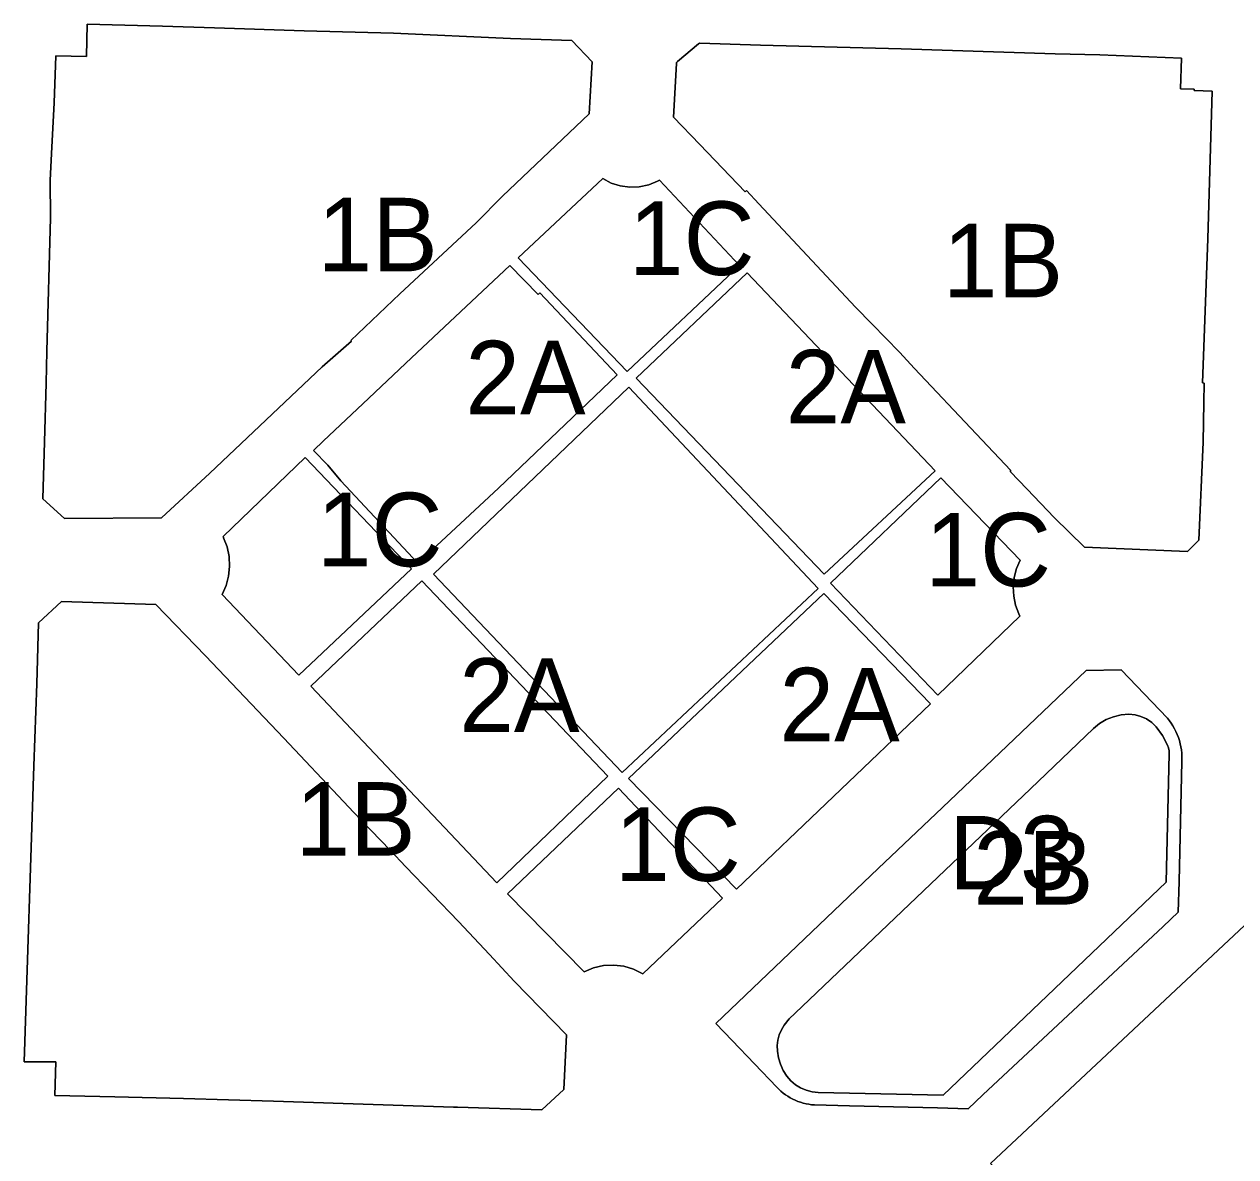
# Model space of a CAD drawing. Extents: x 598968 to 613553, y 4409678 to 4430833.
# Drawn here: x 607200.1 to 607397.8, y 4415081 to 4415265.8 of the extents above; entities that cross this region are included whole.
import ezdxf

# ---------------------------------------------------------------- set-up
doc = ezdxf.new("R2010")
doc.units = 0
for name, color, linetype in [('1', 7, 'Continuous'), ('ZONA 1B. Illes de cases extensives - ANNEX III C', 7, 'Continuous'), ('ZONA 1C. Cases aïllades centrals - ANNEX III C', 7, 'Continuous'), ('ZONA 2A. Fileres de cases - ANNEX III C', 7, 'Continuous'), ('ZONA 2B. Blocs aïllats - ANNEX III C', 7, 'Continuous'), ('ZONES URBANES. Espai lliure privat', 7, 'Continuous')]:
    doc.layers.add(name, color=color, linetype=linetype)

msp = doc.modelspace()

# ---------------------------------------------------------------- linework, layer by layer
at = {"layer": '1'}
for points in [[(607289.4816, 4415263.0751), (607292.7716, 4415259.6052), (607292.2616, 4415251.1253), (607278.1618, 4415237.6852), (607273.8319, 4415233.3751), (607261.3971, 4415221.76), (607253.412, 4415214.1444), (607253.4972, 4415214.055), (607248.7123, 4415209.8549), (607230.4076, 4415192.5248), (607222.4927, 4415185.2347), (607206.7029, 4415185.1145), (607203.1429, 4415188.3444), (607203.4029, 4415197.6243), (607203.6828, 4415207.1641), (607203.7828, 4415212.4141), (607204.3869, 4415234.1644), (607204.3627, 4415240.2838), (607204.6327, 4415245.6737), (607205.0027, 4415252.9437), (607205.2526, 4415260.6136), (607210.2526, 4415260.4937), (607210.388, 4415265.7535), (607222.6524, 4415265.4638), (607231.1423, 4415265.174), (607245.8021, 4415264.6743), (607260.337, 4415264.2845), (607279.4417, 4415263.4049)], [(607393.9298, 4415254.85), (607393.2304, 4415230.7274), (607392.3679, 4415207.226), (607392.6436, 4415207.2159), (607392.5805, 4415204.0277), (607392.4906, 4415197.5877), (607391.7406, 4415181.5479), (607389.8907, 4415179.7279), (607373.1009, 4415180.4576), (607368.1759, 4415185.2974), (607363.7409, 4415189.8873), (607360.961, 4415192.7772), (607361.111, 4415192.9172), (607355.411, 4415198.947), (607345.3911, 4415209.6067), (607342.9411, 4415212.2366), (607338.4811, 4415216.7965), (607335.7412, 4415219.6164), (607319.9713, 4415236.4659), (607317.9663, 4415238.6509), (607317.7413, 4415238.4159), (607310.3314, 4415246.1357), (607306.0515, 4415250.6155), (607306.5114, 4415259.3254), (607306.5244, 4415259.4098), (607306.5508, 4415259.491), (607306.5898, 4415259.567), (607306.6404, 4415259.6357), (607306.7014, 4415259.6954), (607310.1213, 4415262.5455), (607310.161, 4415262.5816), (607310.2062, 4415262.6103), (607310.2556, 4415262.6309), (607310.3078, 4415262.6428), (607310.3613, 4415262.6455), (607320.2212, 4415262.3157), (607343.2109, 4415261.7261), (607368.3106, 4415260.9464), (607375.6205, 4415260.7767), (607388.9288, 4415260.2269), (607388.7504, 4415255.227), (607391.0204, 4415255.137), (607391.0152, 4415254.9469)], [(607297.3677, 4415239.3668), (607298.9127, 4415239.1561), (607300.4708, 4415239.2157), (607301.9951, 4415239.5436), (607303.4397, 4415240.1301), (607303.7615, 4415240.2856), (607316.8414, 4415226.406), (607298.5017, 4415209.1159), (607280.6919, 4415227.6253), (607294.5016, 4415240.5654), (607295.8825, 4415239.8414)], [(607279.3519, 4415226.4053), (607283.9418, 4415221.6455), (607284.2518, 4415221.9355), (607296.8515, 4415208.543), (607277.482, 4415190.0357), (607264.3478, 4415177.7939), (607251.7623, 4415191.2452), (607249.6224, 4415193.7966), (607247.3124, 4415196.1951), (607248.9523, 4415197.7951), (607255.3672, 4415203.8301), (607263.3221, 4415211.3202)], [(607348.7411, 4415192.867), (607330.6378, 4415176.0424), (607299.9517, 4415208.0259), (607318.0414, 4415225.186)], [(607329.6297, 4415173.7121), (607297.6971, 4415143.6501), (607266.8797, 4415176.031), (607298.7815, 4415206.5156)], [(607329.6297, 4415173.7121), (607298.7815, 4415206.5156), (607266.8797, 4415176.031), (607297.6971, 4415143.6501)], [(607263.2922, 4415176.9156), (607244.8925, 4415159.5654), (607232.4026, 4415172.7051), (607233.0383, 4415174.1696), (607233.4433, 4415175.7139), (607233.608, 4415177.3018), (607233.5285, 4415178.8963), (607233.2068, 4415180.46), (607232.6504, 4415181.9564), (607232.6177, 4415182.0583), (607232.5732, 4415182.1556), (607245.9601, 4415195.0655)], [(607362.551, 4415169.1475), (607349.1912, 4415156.2774), (607331.6714, 4415174.5569), (607349.6711, 4415191.767), (607362.601, 4415178.3274), (607362.01, 4415176.9338), (607361.6349, 4415175.4672), (607361.4844, 4415173.9609), (607361.5617, 4415172.4491), (607361.8652, 4415170.9662), (607362.3879, 4415169.5455)], [(607295.312, 4415143.0766), (607277.1976, 4415125.6671), (607246.8725, 4415157.7355), (607265.0122, 4415174.9256)], [(607347.9813, 4415154.8474), (607316.3317, 4415124.6272), (607298.6819, 4415142.6866), (607330.5714, 4415172.8569)], [(607288.1523, 4415091.9271), (607284.5419, 4415088.6349), (607270.8298, 4415089.0581), (607270.1698, 4415089.0797), (607258.6526, 4415089.4566), (607240.7828, 4415090.0362), (607226.123, 4415090.4859), (607214.9199, 4415090.7307), (607205.0833, 4415090.9455), (607205.2432, 4415096.4355), (607200.1133, 4415096.4854), (607201.6731, 4415144.7648), (607202.1454, 4415158.1491), (607202.433, 4415168.0746), (607206.2159, 4415171.5473), (607221.5728, 4415171.0749), (607229.6627, 4415162.7051), (607242.4526, 4415149.2755), (607252.2025, 4415138.9258), (607253.8725, 4415137.1359), (607255.1262, 4415135.8487), (607259.8425, 4415131.006), (607262.3724, 4415128.2962), (607270.9424, 4415119.3664), (607276.0323, 4415113.9566), (607280.0723, 4415109.6267), (607288.5922, 4415100.877)], [(607379.069, 4415160.3997), (607386.6388, 4415152.5401), (607386.9588, 4415152.1203), (607387.2588, 4415151.7003), (607387.5388, 4415151.2603), (607387.7888, 4415150.8003), (607388.0188, 4415150.3303), (607388.2288, 4415149.8603), (607388.4188, 4415149.3703), (607388.5788, 4415148.8703), (607388.7088, 4415148.3703), (607388.8288, 4415147.8603), (607388.9088, 4415147.3404), (607388.9688, 4415146.8204), (607388.9988, 4415146.3005), (607388.9988, 4415145.4705), (607388.529, 4415125.8809), (607388.409, 4415120.8711), (607385.9191, 4415118.551), (607356.54, 4415091.0505), (607354.1101, 4415088.7805), (607349.1302, 4415088.9303), (607334.7806, 4415089.2798), (607329.0407, 4415089.4196), (607328.5807, 4415089.4595), (607328.1207, 4415089.5295), (607327.6707, 4415089.6195), (607327.2207, 4415089.7295), (607326.7807, 4415089.8595), (607326.3408, 4415090.0095), (607325.9108, 4415090.1895), (607325.5008, 4415090.3795), (607325.0908, 4415090.5994), (607324.6908, 4415090.8394), (607324.3108, 4415091.0993), (607323.9408, 4415091.3693), (607323.5808, 4415091.6693), (607323.2408, 4415091.9793), (607322.9208, 4415092.3093), (607315.6309, 4415099.9489), (607312.971, 4415102.7387), (607339.4602, 4415127.9791), (607349.9298, 4415137.9591), (607373.389, 4415160.3095)], [(607314.0618, 4415123.1772), (607301.032, 4415110.8171), (607299.5446, 4415111.5638), (607297.9509, 4415112.0431), (607296.2983, 4415112.2407), (607294.6364, 4415112.1506), (607293.0148, 4415111.7756), (607291.4821, 4415111.1269), (607278.9422, 4415123.8465), (607297.052, 4415141.1266)], [(607406.2436, 4415028.3837), (607357.7665, 4415079.882), (607400.0659, 4415119.5323), (607448.0291, 4415068.3834), (607494.246, 4415066.8294), (607500.435, 4415062.8748), (607499.825, 4415051.5949), (607498.0651, 4415043.685), (607491.9652, 4415032.845), (607490.0452, 4415030.475), (607482.0353, 4415016.935), (607480.3354, 4415012.755), (607477.1754, 4415002.7051), (607475.9355, 4414997.5151), (607474.8055, 4414990.8552), (607474.0155, 4414988.7052), (607472.5456, 4414987.3552), (607471.0256, 4414986.6852), (607467.1856, 4414986.4151), (607404.8763, 4414988.4539)], [(607448.0291, 4415068.3834), (607400.0659, 4415119.5323), (607357.7665, 4415079.882), (607406.2436, 4415028.3837), (607406.4361, 4415034.0034), (607442.4385, 4415068.5714)]]:
    msp.add_lwpolyline(points, close=True, dxfattribs=at)
at = {"layer": 'ZONA 1B. Illes de cases extensives - ANNEX III C'}
for points in [[(607289.4816, 4415263.0751), (607279.4417, 4415263.4049), (607260.337, 4415264.2845), (607245.8021, 4415264.6743), (607231.1423, 4415265.174), (607222.6524, 4415265.4638), (607210.388, 4415265.7535), (607210.2526, 4415260.4937), (607205.2526, 4415260.6136), (607205.0027, 4415252.9437), (607204.6327, 4415245.6737), (607204.3627, 4415240.2838), (607204.3869, 4415234.1644), (607203.7828, 4415212.4141), (607203.6828, 4415207.1641), (607203.4029, 4415197.6243), (607203.1429, 4415188.3444), (607206.7029, 4415185.1145), (607222.4927, 4415185.2347), (607230.4076, 4415192.5248), (607248.7123, 4415209.8549), (607253.4972, 4415214.055), (607253.412, 4415214.1444), (607261.3971, 4415221.76), (607273.8319, 4415233.3751), (607278.1618, 4415237.6852), (607292.2616, 4415251.1253), (607292.7716, 4415259.6052)], [(607393.9298, 4415254.85), (607391.0152, 4415254.9469), (607391.0204, 4415255.137), (607388.7504, 4415255.227), (607388.9288, 4415260.2269), (607375.6205, 4415260.7767), (607368.3106, 4415260.9464), (607343.2109, 4415261.7261), (607320.2212, 4415262.3157), (607310.3613, 4415262.6455), (607310.3078, 4415262.6428), (607310.2556, 4415262.6309), (607310.2062, 4415262.6103), (607310.161, 4415262.5816), (607310.1213, 4415262.5455), (607306.7014, 4415259.6954), (607306.6404, 4415259.6357), (607306.5898, 4415259.567), (607306.5508, 4415259.491), (607306.5244, 4415259.4098), (607306.5114, 4415259.3254), (607306.0515, 4415250.6155), (607310.3314, 4415246.1357), (607317.7413, 4415238.4159), (607317.9663, 4415238.6509), (607319.9713, 4415236.4659), (607335.7412, 4415219.6164), (607338.4811, 4415216.7965), (607342.9411, 4415212.2366), (607345.3911, 4415209.6067), (607355.411, 4415198.947), (607361.111, 4415192.9172), (607360.961, 4415192.7772), (607363.7409, 4415189.8873), (607368.1759, 4415185.2974), (607373.1009, 4415180.4576), (607389.8907, 4415179.7279), (607391.7406, 4415181.5479), (607392.4906, 4415197.5877), (607392.5805, 4415204.0277), (607392.6436, 4415207.2159), (607392.3679, 4415207.226), (607393.2304, 4415230.7274)], [(607288.1523, 4415091.9271), (607288.5922, 4415100.877), (607280.0723, 4415109.6267), (607276.0323, 4415113.9566), (607270.9424, 4415119.3664), (607262.3724, 4415128.2962), (607259.8425, 4415131.006), (607255.1262, 4415135.8487), (607253.8725, 4415137.1359), (607252.2025, 4415138.9258), (607242.4526, 4415149.2755), (607229.6627, 4415162.7051), (607221.5728, 4415171.0749), (607206.2159, 4415171.5473), (607202.433, 4415168.0746), (607202.1454, 4415158.1491), (607201.6731, 4415144.7648), (607200.1133, 4415096.4854), (607205.2432, 4415096.4355), (607205.0833, 4415090.9455), (607214.9199, 4415090.7307), (607226.123, 4415090.4859), (607240.7828, 4415090.0362), (607258.6526, 4415089.4566), (607270.1698, 4415089.0797), (607270.8298, 4415089.0581), (607284.5419, 4415088.6349)]]:
    msp.add_lwpolyline(points, close=True, dxfattribs=at)
at = {"layer": 'ZONA 1C. Cases aïllades centrals - ANNEX III C'}
for points in [[(607297.3677, 4415239.3668), (607295.8825, 4415239.8414), (607294.5016, 4415240.5654), (607280.6919, 4415227.6253), (607298.5017, 4415209.1159), (607316.8414, 4415226.406), (607303.7615, 4415240.2856), (607303.4397, 4415240.1301), (607301.9951, 4415239.5436), (607300.4708, 4415239.2157), (607298.9127, 4415239.1561)], [(607263.2922, 4415176.9156), (607245.9601, 4415195.0655), (607232.5732, 4415182.1556), (607232.6177, 4415182.0583), (607232.6504, 4415181.9564), (607233.2068, 4415180.46), (607233.5285, 4415178.8963), (607233.608, 4415177.3018), (607233.4433, 4415175.7139), (607233.0383, 4415174.1696), (607232.4026, 4415172.7051), (607244.8925, 4415159.5654)], [(607362.551, 4415169.1475), (607362.3879, 4415169.5455), (607361.8652, 4415170.9662), (607361.5617, 4415172.4491), (607361.4844, 4415173.9609), (607361.6349, 4415175.4672), (607362.01, 4415176.9338), (607362.601, 4415178.3274), (607349.6711, 4415191.767), (607331.6714, 4415174.5569), (607349.1912, 4415156.2774)], [(607314.0618, 4415123.1772), (607297.052, 4415141.1266), (607278.9422, 4415123.8465), (607291.4821, 4415111.1269), (607293.0148, 4415111.7756), (607294.6364, 4415112.1506), (607296.2983, 4415112.2407), (607297.9509, 4415112.0431), (607299.5446, 4415111.5638), (607301.032, 4415110.8171)]]:
    msp.add_lwpolyline(points, close=True, dxfattribs=at)
at = {"layer": 'ZONA 2A. Fileres de cases - ANNEX III C'}
for points in [[(607279.3519, 4415226.4053), (607263.3221, 4415211.3202), (607255.3672, 4415203.8301), (607248.9523, 4415197.7951), (607247.3124, 4415196.1951), (607249.6224, 4415193.7966), (607251.7623, 4415191.2452), (607264.3478, 4415177.7939), (607277.482, 4415190.0357), (607296.8515, 4415208.543), (607284.2518, 4415221.9355), (607283.9418, 4415221.6455)], [(607348.7411, 4415192.867), (607318.0414, 4415225.186), (607299.9517, 4415208.0259), (607330.6378, 4415176.0424)], [(607295.312, 4415143.0766), (607265.0122, 4415174.9256), (607246.8725, 4415157.7355), (607277.1976, 4415125.6671)], [(607347.9813, 4415154.8474), (607330.5714, 4415172.8569), (607298.6819, 4415142.6866), (607316.3317, 4415124.6272)]]:
    msp.add_lwpolyline(points, close=True, dxfattribs=at)
at = {"layer": 'ZONA 2B. Blocs aïllats - ANNEX III C'}
msp.add_lwpolyline([(607386.4109, 4415125.7585), (607386.9408, 4415146.7382), (607386.9108, 4415147.2161), (607386.8169, 4415147.6856), (607386.6608, 4415148.1382), (607385.8467, 4415149.7094), (607384.7958, 4415151.1331), (607384.0722, 4415151.8351), (607383.2391, 4415152.4031), (607382.3214, 4415152.8203), (607381.3457, 4415153.0744), (607380.3409, 4415153.158), (607379.0692, 4415153.0575), (607377.8273, 4415152.7653), (607376.6441, 4415152.2884), (607375.5469, 4415151.6375), (607374.561, 4415150.8279), (607364.2761, 4415140.9829), (607325.9017, 4415104.4176), (607324.9382, 4415103.48), (607324.1017, 4415102.4276), (607323.6458, 4415101.6631), (607323.3012, 4415100.8424), (607323.0749, 4415099.9815), (607322.9711, 4415099.0975), (607322.9918, 4415098.2076), (607323.1686, 4415097.1183), (607323.4902, 4415096.0626), (607323.9507, 4415095.0597), (607324.5418, 4415094.1277), (607325.1862, 4415093.3765), (607325.9373, 4415092.7321), (607326.7778, 4415092.2094), (607327.688, 4415091.8207), (607328.6468, 4415091.5749), (607329.6317, 4415091.4778), (607342.4216, 4415091.1981), (607350.0215, 4415091.0382)], close=True, dxfattribs=at)
at = {"layer": 'ZONES URBANES. Espai lliure privat'}
for points in [[(607379.069, 4415160.3997), (607373.389, 4415160.3095), (607349.9298, 4415137.9591), (607339.4602, 4415127.9791), (607312.971, 4415102.7387), (607315.6309, 4415099.9489), (607322.9208, 4415092.3093), (607323.2408, 4415091.9793), (607323.5808, 4415091.6693), (607323.9408, 4415091.3693), (607324.3108, 4415091.0993), (607324.6908, 4415090.8394), (607325.0908, 4415090.5994), (607325.5008, 4415090.3795), (607325.9108, 4415090.1895), (607326.3408, 4415090.0095), (607326.7807, 4415089.8595), (607327.2207, 4415089.7295), (607327.6707, 4415089.6195), (607328.1207, 4415089.5295), (607328.5807, 4415089.4595), (607329.0407, 4415089.4196), (607334.7806, 4415089.2798), (607349.1302, 4415088.9303), (607354.1101, 4415088.7805), (607356.54, 4415091.0505), (607385.9191, 4415118.551), (607388.409, 4415120.8711), (607388.529, 4415125.8809), (607388.9988, 4415145.4705), (607388.9988, 4415146.3005), (607388.9688, 4415146.8204), (607388.9088, 4415147.3404), (607388.8288, 4415147.8603), (607388.7088, 4415148.3703), (607388.5788, 4415148.8703), (607388.4188, 4415149.3703), (607388.2288, 4415149.8603), (607388.0188, 4415150.3303), (607387.7888, 4415150.8003), (607387.5388, 4415151.2603), (607387.2588, 4415151.7003), (607386.9588, 4415152.1203), (607386.6388, 4415152.5401)], [(607386.4109, 4415125.7585), (607350.0215, 4415091.0382), (607342.4216, 4415091.1981), (607329.6317, 4415091.4778), (607328.6468, 4415091.5749), (607327.688, 4415091.8207), (607326.7778, 4415092.2094), (607325.9373, 4415092.7321), (607325.1862, 4415093.3765), (607324.5418, 4415094.1277), (607323.9507, 4415095.0597), (607323.4902, 4415096.0626), (607323.1686, 4415097.1183), (607322.9918, 4415098.2076), (607322.9711, 4415099.0975), (607323.0749, 4415099.9815), (607323.3012, 4415100.8424), (607323.6458, 4415101.6631), (607324.1017, 4415102.4276), (607324.9382, 4415103.48), (607325.9017, 4415104.4176), (607364.2761, 4415140.9829), (607374.561, 4415150.8279), (607375.5469, 4415151.6375), (607376.6441, 4415152.2884), (607377.8273, 4415152.7653), (607379.0692, 4415153.0575), (607380.3409, 4415153.158), (607381.3457, 4415153.0744), (607382.3214, 4415152.8203), (607383.2391, 4415152.4031), (607384.0722, 4415151.8351), (607384.7958, 4415151.1331), (607385.8467, 4415149.7094), (607386.6608, 4415148.1382), (607386.8169, 4415147.6856), (607386.9108, 4415147.2161), (607386.9408, 4415146.7382)]]:
    msp.add_lwpolyline(points, close=True, dxfattribs=at)

# ---------------------------------------------------------------- texts
at = {"layer": 'ZONA 1B. Illes de cases extensives - ANNEX III C'}
for p in [(607247.9572, 4415225.434), (607349.9907, 4415221.1867), (607244.3528, 4415130.0911)]:
    msp.add_text('1B', height=12, dxfattribs=at).set_placement(p)
at = {"layer": 'ZONA 1C. Cases aïllades centrals - ANNEX III C'}
for p in [(607298.7667, 4415224.8407), (607247.8474, 4415177.3155), (607347.1362, 4415174.0222), (607296.502, 4415125.9718)]:
    msp.add_text('1C', height=12, dxfattribs=at).set_placement(p)
at = {"layer": 'ZONA 2A. Fileres de cases - ANNEX III C'}
for p in [(607272.082, 4415202.0996), (607324.3464, 4415200.6142), (607271.0922, 4415150.2963), (607323.3316, 4415148.742)]:
    msp.add_text('2A', height=12, dxfattribs=at).set_placement(p)
at = {"layer": 'ZONA 2B. Blocs aïllats - ANNEX III C'}
msp.add_text('2B', height=12, dxfattribs=at).set_placement((607354.9559, 4415122.0981))
at = {"layer": 'ZONES URBANES. Espai lliure privat'}
msp.add_text('D3', height=12, dxfattribs=at).set_placement((607350.9849, 4415124.5901))

doc.saveas('drawing.dxf')
